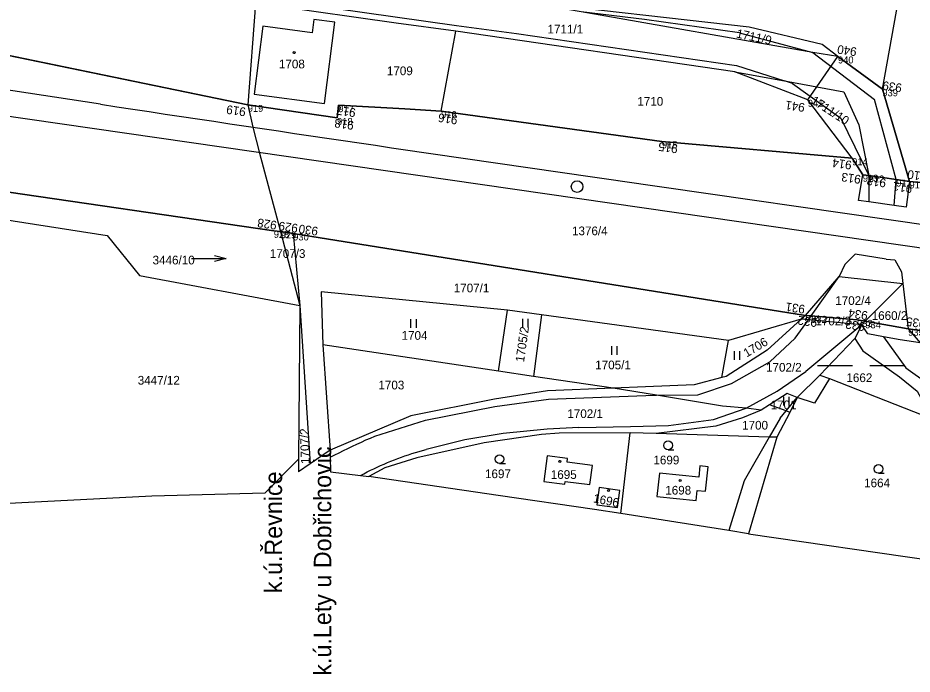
# Model space of a CAD drawing. Extents: x -757895 to -757311, y -1060303 to -1059942.
# Drawn here: x -757679.5 to -757525.5, y -1060222.2 to -1060109.2 of the extents above; entities that cross this region are included whole.
import ezdxf

# ---------------------------------------------------------------- set-up
doc = ezdxf.new("R2010")
doc.units = 0
for name, color, linetype in [('_SO 102 hektometry', 7, 'Continuous'), ('Dočasné zábory', 7, 'Continuous'), ('Obvod stavby', 7, 'Continuous'), ('Vrstva 1', 7, 'Continuous'), ('Vrstva 53', 7, 'Continuous'), ('Vrstva 55', 7, 'Continuous'), ('Vrstva 56', 7, 'Continuous'), ('Vrstva 57', 7, 'Continuous'), ('Vrstva 58', 7, 'Continuous'), ('Vrstva 59', 7, 'Continuous'), ('Vrstva 60', 7, 'Continuous')]:
    doc.layers.add(name, color=color, linetype=linetype)

msp = doc.modelspace()

# ---------------------------------------------------------------- linework, layer by layer
at = {"layer": '_SO 102 hektometry'}
msp.add_circle((-757583.22, -1060138.24), 1, dxfattribs=at)
at = {"layer": 'Dočasné zábory'}
msp.add_lwpolyline([(-757538.3, -1060115.83), (-757530.66, -1060121.48), (-757525.99, -1060137.35), (-757528.28, -1060137.03), (-757533.01, -1060136.32), (-757534.03, -1060136.19), (-757535.86, -1060133.35), (-757543.49, -1060123.29), (-757538.3, -1060115.83)], dxfattribs=at)
at = {"layer": 'Obvod stavby'}
for points in [[(-757420.49, -1060174.29), (-757417.66, -1060153.97), (-757419.22, -1060153.71), (-757450.04, -1060148.6), (-757493.93, -1060141.33), (-757496.99, -1060140.91), (-757515.4, -1060138.37), (-757520.85, -1060137.84), (-757523.49, -1060137.59), (-757525.99, -1060137.35), (-757528.28, -1060137.03), (-757533.01, -1060136.32), (-757534.03, -1060136.19), (-757535.86, -1060133.35), (-757568.62, -1060130.44), (-757606.63, -1060125.23), (-757624.32, -1060124.22), (-757624.54, -1060126.42), (-757639.93, -1060124.17), (-757687.19, -1060114.38)], [(-757686.64, -1060138.39), (-757635.44, -1060145.86), (-757634.26, -1060145.96), (-757632.1, -1060146.3), (-757543.88, -1060160.4), (-757542.9, -1060160.49), (-757535.01, -1060161.18), (-757533.6, -1060161.43), (-757526.21, -1060162.71), (-757513.1, -1060164.5), (-757470.38, -1060167.04), (-757443.58, -1060171.99), (-757420.49, -1060174.29)]]:
    msp.add_lwpolyline(points, dxfattribs=at)
at = {"layer": 'Vrstva 1'}
for p, q in [((-757429.32, -1060162.53), (-757720.62, -1060120.47)), ((-757665.26, -1060124.05), (-757689.98, -1060120.32)), ((-757576.18, -1060137.2), (-757470.2, -1060152.45))]:
    msp.add_line(p, q, dxfattribs=at)
msp.add_arc((-755796.09, -1047764.6), 12500, 261.400126, 261.812855, dxfattribs=at)
at = {"layer": 'Vrstva 53'}
for points in [[(-757687.19, -1060114.38), (-757639.93, -1060124.17), (-757624.54, -1060126.42), (-757624.32, -1060124.22), (-757612.89, -1060124.84), (-757606.63, -1060125.23), (-757568.62, -1060130.44), (-757535.86, -1060133.35), (-757534.03, -1060136.19), (-757533.01, -1060136.32), (-757528.28, -1060137.03), (-757525.99, -1060137.35), (-757523.49, -1060137.59), (-757520.85, -1060137.84), (-757515.4, -1060138.37), (-757496.99, -1060140.91), (-757493.93, -1060141.33), (-757450.04, -1060148.6), (-757417.66, -1060153.97), (-757412.43, -1060151.61), (-757391.89, -1060154.81), (-757390.25, -1060143), (-757387.56, -1060158.16)], [(-757328.56, -1060183.46), (-757338.29, -1060184.85), (-757361.91, -1060181.63), (-757443.58, -1060171.99), (-757470.38, -1060167.04), (-757513.1, -1060164.5), (-757526.21, -1060162.71), (-757533.6, -1060161.43), (-757535.01, -1060161.18), (-757542.9, -1060160.49), (-757543.88, -1060160.4), (-757632.1, -1060146.3), (-757634.26, -1060145.96), (-757635.44, -1060145.86), (-757686.64, -1060138.39), (-757693.18, -1060137.43), (-757732.62, -1060131.67), (-757793.56, -1060122.78), (-757866, -1060118.97)]]:
    msp.add_lwpolyline(points, dxfattribs=at)
at = {"layer": 'Vrstva 55'}
for p, q in [((-757638.59, -1060106.69), (-757639.93, -1060124.17)), ((-757638.59, -1060106.69), (-757639.93, -1060124.17)), ((-757530.66, -1060121.48), (-757527.8, -1060105.72)), ((-757606.63, -1060125.23), (-757604.11, -1060111.45)), ((-757556.06, -1060118.47), (-757604.11, -1060111.45)), ((-757687.19, -1060114.38), (-757639.93, -1060124.17)), ((-757530.66, -1060121.48), (-757538.3, -1060115.83)), ((-757525.99, -1060137.35), (-757530.66, -1060121.48)), ((-757634.26, -1060145.96), (-757632.1, -1060146.3)), ((-757634.26, -1060145.96), (-757630.94, -1060158.73)), ((-757634.26, -1060145.96), (-757630.94, -1060158.73)), ((-757632.1, -1060146.3), (-757543.88, -1060160.4)), ((-757632.1, -1060146.3), (-757630.94, -1060158.73)), ((-757527.15, -1060154.92), (-757533.6, -1060161.43)), ((-757527.15, -1060154.92), (-757526.21, -1060162.71)), ((-757630.94, -1060158.73), (-757631.18, -1060185.19)), ((-757630.94, -1060158.73), (-757631.18, -1060185.19)), ((-757630.94, -1060158.73), (-757629.16, -1060185.96)), ((-757596.77, -1060170), (-757595.21, -1060159.51)), ((-757589.33, -1060160.31), (-757595.21, -1060159.51)), ((-757589.33, -1060160.31), (-757590.73, -1060170.9)), ((-757557.15, -1060164.71), (-757589.33, -1060160.31)), ((-757543.88, -1060160.4), (-757544.63, -1060161.07)), ((-757544.63, -1060161.07), (-757557.15, -1060164.71)), ((-757534.18, -1060162.01), (-757535.4, -1060164.4)), ((-757533.6, -1060161.43), (-757534.18, -1060162.01)), ((-757533.6, -1060161.43), (-757526.21, -1060162.71)), ((-757526.21, -1060162.71), (-757513.1, -1060164.5)), ((-757558.32, -1060171.12), (-757557.15, -1060164.71)), ((-757535.4, -1060164.4), (-757541.4, -1060170.7)), ((-757627, -1060165.49), (-757625.74, -1060183.63)), ((-757596.77, -1060170), (-757627, -1060165.49)), ((-757590.73, -1060170.9), (-757596.77, -1060170)), ((-757576.99, -1060172.95), (-757590.73, -1060170.9)), ((-757541.4, -1060170.7), (-757545.33, -1060174.55)), ((-757545.33, -1060174.55), (-757546.6, -1060177.1)), ((-757550.1, -1060175.8), (-757551.51, -1060176.74)), ((-757546.6, -1060177.1), (-757548.85, -1060181.4)), ((-757575.67, -1060194.52), (-757574.09, -1060180.62)), ((-757569.63, -1060180.73), (-757574.09, -1060180.62)), ((-757548.85, -1060181.4), (-757553.73, -1060197.99)), ((-757625.74, -1060183.63), (-757629.16, -1060185.96)), ((-757631.18, -1060185.19), (-757636.9, -1060190.98)), ((-757631.18, -1060185.19), (-757631.2, -1060187.35)), ((-757629.16, -1060185.96), (-757631.2, -1060187.35)), ((-757596.81, -1060191.42), (-757619.09, -1060188.12)), ((-757580.24, -1060193.85), (-757596.81, -1060191.42)), ((-757575.67, -1060194.52), (-757580.24, -1060193.85)), ((-757553.73, -1060197.99), (-757501.45, -1060205.62))]:
    msp.add_line(p, q, dxfattribs=at)
for points in [[(-757643.18, -1060052.41), (-757642.66, -1060069.92), (-757642.17, -1060087.53), (-757638.59, -1060106.69), (-757639.93, -1060124.17), (-757639.03, -1060128.02), (-757637.9, -1060132.49), (-757634.26, -1060145.96), (-757630.94, -1060158.73), (-757631.18, -1060185.19), (-757631.2, -1060187.35)], [(-757538.3, -1060115.83), (-757542.65, -1060115.17), (-757582.51, -1060108.15), (-757593.23, -1060106.29)], [(-757538.3, -1060115.83), (-757541.05, -1060113.79), (-757553.6, -1060110.8), (-757593.23, -1060106.29)], [(-757604.11, -1060111.45), (-757614.37, -1060110.07), (-757635.45, -1060107.13)], [(-757637.32, -1060110.63), (-757638.83, -1060122.33), (-757626.73, -1060123.9), (-757624.93, -1060109.9), (-757628.52, -1060109.44), (-757628.82, -1060111.73), (-757637.32, -1060110.63)], [(-757535.86, -1060133.35), (-757543.49, -1060123.29), (-757556.06, -1060118.47)], [(-757556.06, -1060118.47), (-757547.51, -1060120.04), (-757537.32, -1060121.92), (-757534.73, -1060127.58), (-757533.01, -1060136.32)], [(-757606.63, -1060125.23), (-757612.89, -1060124.84), (-757624.32, -1060124.22), (-757624.54, -1060126.42), (-757639.93, -1060124.17)], [(-757639.93, -1060124.17), (-757639.03, -1060128.02), (-757637.9, -1060132.49), (-757634.26, -1060145.96)], [(-757639.93, -1060124.17), (-757639.03, -1060128.02), (-757637.9, -1060132.49), (-757634.26, -1060145.96)], [(-757535.86, -1060133.35), (-757568.62, -1060130.44), (-757606.63, -1060125.23)], [(-757533.01, -1060136.32), (-757534.03, -1060136.19), (-757535.86, -1060133.35)], [(-757525.99, -1060137.35), (-757528.28, -1060137.03), (-757533.01, -1060136.32)], [(-757515.4, -1060138.37), (-757518.94, -1060138.03), (-757520.85, -1060137.84), (-757523.49, -1060137.59), (-757525.99, -1060137.35)], [(-757634.26, -1060145.96), (-757635.44, -1060145.86), (-757686.64, -1060138.39)], [(-757686.61, -1060143.18), (-757664.14, -1060146.65), (-757658.56, -1060153.53), (-757630.94, -1060158.73)], [(-757543.88, -1060160.4), (-757538.07, -1060153.7), (-757527.15, -1060154.92)], [(-757595.21, -1060159.51), (-757627.27, -1060156.33), (-757627, -1060165.49)], [(-757533.6, -1060161.43), (-757535.01, -1060161.18), (-757542.9, -1060160.49), (-757543.88, -1060160.4)], [(-757544.63, -1060161.07), (-757550.52, -1060166.39), (-757557.55, -1060170.92), (-757558.32, -1060171.12)], [(-757534.18, -1060162.01), (-757543.4, -1060161.18), (-757544.63, -1060161.07)], [(-757530.47, -1060164.08), (-757533.19, -1060163.6), (-757534.18, -1060162.01)], [(-757535.4, -1060164.4), (-757534.05, -1060166.5), (-757527.72, -1060171), (-757524.67, -1060173.45), (-757522.06, -1060178.2)], [(-757530.47, -1060164.08), (-757526.6, -1060169.42), (-757519.47, -1060174.52), (-757512.04, -1060178.07), (-757508.94, -1060181.82), (-757502, -1060190.6), (-757494.7, -1060204.13)], [(-757512.14, -1060167.1), (-757524.18, -1060165.15), (-757527.62, -1060164.59), (-757530.47, -1060164.08)], [(-757558.32, -1060171.12), (-757563.04, -1060172.38), (-757571.43, -1060172.73), (-757576.99, -1060172.95)], [(-757541.4, -1060170.7), (-757539.76, -1060171.25), (-757522.06, -1060178.2)], [(-757576.99, -1060172.95), (-757588.33, -1060173.41), (-757597.42, -1060174.85), (-757611.84, -1060177.68), (-757625.74, -1060183.63)], [(-757551.51, -1060176.74), (-757554.09, -1060176.38), (-757558.16, -1060176.02), (-757569.54, -1060174.17), (-757576.99, -1060172.95)], [(-757545.33, -1060174.55), (-757547.04, -1060173.83), (-757550.1, -1060175.8)], [(-757546.6, -1060177.1), (-757547.24, -1060176.86), (-757550.1, -1060175.8)], [(-757551.51, -1060176.74), (-757554.73, -1060178.07), (-757559.36, -1060179.48), (-757569.63, -1060180.73)], [(-757574.09, -1060180.62), (-757586.32, -1060180.67), (-757589.35, -1060180.9), (-757599.24, -1060182.35), (-757610.82, -1060184.91), (-757616.3, -1060186.63), (-757619.09, -1060188.12)], [(-757548.85, -1060181.4), (-757550.13, -1060181.36), (-757569.63, -1060180.73)], [(-757625.74, -1060183.63), (-757625.72, -1060184.84), (-757625.67, -1060187.37)], [(-757580.59, -1060186.26), (-757584.93, -1060185.69), (-757584.85, -1060185.07), (-757588.36, -1060184.6), (-757588.94, -1060189.01), (-757585.35, -1060189.49), (-757585.29, -1060188.99), (-757581.03, -1060189.55), (-757580.59, -1060186.26)], [(-757569.05, -1060187.55), (-757569.49, -1060191.57), (-757562.71, -1060192.3), (-757562.52, -1060190.53), (-757561.12, -1060190.68), (-757560.66, -1060186.46), (-757562.06, -1060186.31), (-757562.27, -1060188.28), (-757569.05, -1060187.55)], [(-757625.67, -1060187.37), (-757620.5, -1060187.96), (-757619.09, -1060188.12)], [(-757684.44, -1060192.89), (-757656.46, -1060191.47), (-757636.9, -1060190.98)], [(-757579.43, -1060190.03), (-757579.85, -1060193), (-757576.28, -1060193.51), (-757575.85, -1060190.54), (-757579.43, -1060190.03)], [(-757553.73, -1060197.99), (-757557.09, -1060197.46), (-757573.5, -1060194.87), (-757575.67, -1060194.52)]]:
    msp.add_lwpolyline(points, dxfattribs=at)
at = {"layer": 'Vrstva 56'}
for p, q in [((-757625.12, -1060107.53), (-757604, -1060110.48)), ((-757571.64, -1060109.48), (-757582.51, -1060108.15)), ((-757555.27, -1060111.76), (-757571.64, -1060109.48)), ((-757604, -1060110.48), (-757593.68, -1060111.85)), ((-757593.68, -1060111.85), (-757555.79, -1060117.41)), ((-757555.27, -1060111.76), (-757542.65, -1060115.17)), ((-757542.65, -1060115.17), (-757532.02, -1060123.21)), ((-757555.79, -1060117.41), (-757547.51, -1060120.04)), ((-757546.14, -1060120.48), (-757547.51, -1060120.04)), ((-757546.14, -1060120.48), (-757537.81, -1060126.43)), ((-757528.28, -1060137.03), (-757532.02, -1060123.21)), ((-757537.81, -1060126.43), (-757533.01, -1060136.32)), ((-757534.76, -1060140.62), (-757534.03, -1060136.19)), ((-757533.01, -1060136.32), (-757532.98, -1060140.88)), ((-757528.61, -1060141.49), (-757528.28, -1060137.03)), ((-757525.99, -1060137.35), (-757526.57, -1060141.77)), ((-757532.98, -1060140.88), (-757534.76, -1060140.62)), ((-757528.61, -1060141.49), (-757532.98, -1060140.88)), ((-757526.57, -1060141.77), (-757528.61, -1060141.49)), ((-757535.34, -1060149.89), (-757537.11, -1060151.64)), ((-757530.01, -1060150.73), (-757535.34, -1060149.89)), ((-757530.01, -1060150.73), (-757528.53, -1060150.83)), ((-757528.53, -1060150.83), (-757527.39, -1060152.92)), ((-757537.11, -1060151.64), (-757538.07, -1060153.7)), ((-757527.39, -1060152.92), (-757527.15, -1060154.92)), ((-757542.9, -1060160.49), (-757538.07, -1060153.7)), ((-757543.4, -1060161.18), (-757542.9, -1060160.49)), ((-757545.65, -1060164.34), (-757543.4, -1060161.18)), ((-757534.18, -1060162.01), (-757543.82, -1060170.07)), ((-757526.21, -1060162.71), (-757524.18, -1060165.15)), ((-757550.01, -1060168.4), (-757545.65, -1060164.34)), ((-757556.62, -1060172.15), (-757550.01, -1060168.4)), ((-757548.76, -1060173.47), (-757543.82, -1060170.07)), ((-757539.76, -1060171.25), (-757542.34, -1060175.54)), ((-757562.46, -1060174.07), (-757556.62, -1060172.15)), ((-757588.16, -1060174.83), (-757571.4, -1060174.19)), ((-757571.4, -1060174.19), (-757569.54, -1060174.17)), ((-757569.54, -1060174.17), (-757562.46, -1060174.07)), ((-757554.09, -1060176.38), (-757548.76, -1060173.47)), ((-757547.24, -1060176.86), (-757545.33, -1060174.55)), ((-757542.34, -1060175.54), (-757545.33, -1060174.55)), ((-757609.33, -1060178.42), (-757597.39, -1060176.11)), ((-757597.39, -1060176.11), (-757588.16, -1060174.83)), ((-757559.73, -1060178.32), (-757554.09, -1060176.38)), ((-757548.27, -1060178.12), (-757547.24, -1060176.86)), ((-757618.02, -1060181.19), (-757609.33, -1060178.42)), ((-757567.48, -1060179.37), (-757559.73, -1060178.32)), ((-757548.27, -1060178.12), (-757550.13, -1060181.36)), ((-757595.94, -1060180.77), (-757602.57, -1060181.84)), ((-757588.4, -1060179.97), (-757595.94, -1060180.77)), ((-757582.91, -1060179.71), (-757588.4, -1060179.97)), ((-757582.91, -1060179.71), (-757574.04, -1060179.54)), ((-757574.04, -1060179.54), (-757567.48, -1060179.37)), ((-757602.57, -1060181.84), (-757609.19, -1060183.49)), ((-757550.13, -1060181.36), (-757554.44, -1060188.87)), ((-757554.44, -1060188.87), (-757557.09, -1060197.46))]:
    msp.add_line(p, q, dxfattribs=at)
for points in [[(-757625.72, -1060184.84), (-757624.96, -1060184.44), (-757624.21, -1060184.05), (-757623.45, -1060183.67), (-757622.68, -1060183.3), (-757621.91, -1060182.93), (-757621.14, -1060182.57), (-757620.36, -1060182.21), (-757619.59, -1060181.86), (-757618.8, -1060181.52), (-757618.02, -1060181.19)], [(-757620.5, -1060187.96), (-757619.93, -1060187.66), (-757619.36, -1060187.36), (-757618.79, -1060187.08), (-757618.21, -1060186.8), (-757617.63, -1060186.53), (-757617.05, -1060186.26), (-757616.46, -1060186), (-757615.87, -1060185.75), (-757615.28, -1060185.51), (-757614.68, -1060185.27), (-757614.08, -1060185.05), (-757613.48, -1060184.82), (-757612.87, -1060184.61), (-757612.26, -1060184.41), (-757611.65, -1060184.21), (-757611.04, -1060184.02), (-757610.43, -1060183.83), (-757609.81, -1060183.66), (-757609.19, -1060183.49)]]:
    msp.add_lwpolyline(points, dxfattribs=at)
at = {"layer": 'Vrstva 58'}
for p, q in [((-757649.63, -1060150.62), (-757643.63, -1060150.62)), ((-757611.9, -1060161.05), (-757611.9, -1060162.55)), ((-757610.9, -1060162.55), (-757610.9, -1060161.05)), ((-757592.64, -1060161.02), (-757592.64, -1060162.52)), ((-757591.64, -1060162.52), (-757591.64, -1060161.02)), ((-757577.3, -1060165.68), (-757577.3, -1060167.18)), ((-757576.3, -1060167.18), (-757576.3, -1060165.68)), ((-757556.2, -1060166.55), (-757556.2, -1060168.05)), ((-757555.2, -1060168.05), (-757555.2, -1060166.55)), ((-757541.83, -1060169.03), (-757535.83, -1060169.03)), ((-757532.83, -1060169.03), (-757526.83, -1060169.03)), ((-757547.68, -1060174.43), (-757547.68, -1060175.93)), ((-757546.68, -1060175.93), (-757546.68, -1060174.43)), ((-757567.56, -1060183.53), (-757566.56, -1060183.53)), ((-757596.57, -1060185.91), (-757595.57, -1060185.91)), ((-757531.34, -1060187.6), (-757530.34, -1060187.6))]:
    msp.add_line(p, q, dxfattribs=at)
msp.add_lwpolyline([(-757645.63, -1060150.12), (-757643.63, -1060150.62), (-757645.63, -1060151.12)], dxfattribs=at)
for centre in [(-757567.56, -1060182.78), (-757596.57, -1060185.16), (-757531.34, -1060186.85)]:
    msp.add_circle(centre, 0.75, dxfattribs=at)
at = {"layer": 'Vrstva 59'}
for centre in [(-757631.95, -1060115.17), (-757586.19, -1060185.54), (-757565.49, -1060188.83), (-757577.81, -1060190.55)]:
    msp.add_circle(centre, 0.175, dxfattribs=at)
at = {"layer": 'Vrstva 60'}
for p, q in [((-757538.3, -1060115.83), (-757538.3, -1060115.83)), ((-757530.66, -1060121.48), (-757530.66, -1060121.48)), ((-757543.49, -1060123.29), (-757543.49, -1060123.29)), ((-757639.93, -1060124.17), (-757639.93, -1060124.17)), ((-757624.32, -1060124.22), (-757624.32, -1060124.22)), ((-757606.63, -1060125.23), (-757606.63, -1060125.23)), ((-757624.54, -1060126.42), (-757624.54, -1060126.42)), ((-757568.62, -1060130.44), (-757568.62, -1060130.44)), ((-757535.86, -1060133.35), (-757535.86, -1060133.35)), ((-757534.03, -1060136.19), (-757534.03, -1060136.19)), ((-757533.01, -1060136.32), (-757533.01, -1060136.32)), ((-757528.28, -1060137.03), (-757528.28, -1060137.03)), ((-757525.99, -1060137.35), (-757525.99, -1060137.35)), ((-757635.44, -1060145.86), (-757635.44, -1060145.86)), ((-757634.26, -1060145.96), (-757634.26, -1060145.96)), ((-757632.1, -1060146.3), (-757632.1, -1060146.3)), ((-757543.88, -1060160.4), (-757543.88, -1060160.4)), ((-757542.9, -1060160.49), (-757542.9, -1060160.49)), ((-757535.01, -1060161.18), (-757535.01, -1060161.18)), ((-757533.6, -1060161.43), (-757533.6, -1060161.43)), ((-757526.21, -1060162.71), (-757526.21, -1060162.71))]:
    msp.add_line(p, q, dxfattribs=at)

# ---------------------------------------------------------------- texts
at = {"layer": 'Dočasné zábory'}
for s, p in [('940', (-757534.99, -1060114.31)), ('939', (-757527.21, -1060120.54)), ('941', (-757543.92, -1060123.91))]:
    msp.add_text(s, height=1.5, rotation=171.7882, dxfattribs=at).set_placement(p)
at = {"layer": 'Obvod stavby'}
for s, p in [('919', (-757640.17, -1060124.67)), ('917', (-757621.25, -1060124.81)), ('918', (-757621.57, -1060127)), ('916', (-757603.71, -1060126.07)), ('915', (-757565.8, -1060131.05)), ('914', (-757535.85, -1060133.84)), ('913', (-757534.28, -1060136.29)), ('910', (-757522.92, -1060135.83)), ('912', (-757529.93, -1060136.92)), ('911', (-757525.41, -1060137.9)), ('928', (-757634.84, -1060144.19)), ('929', (-757631.19, -1060144.71)), ('930', (-757627.73, -1060145.22)), ('931', (-757543.89, -1060158.65)), ('932', (-757541.8, -1060160.96)), ('934', (-757533.08, -1060159.74)), ('935', (-757523.15, -1060161.17)), ('933', (-757533.58, -1060161.65))]:
    msp.add_text(s, height=1.5, rotation=171.7882, dxfattribs=at).set_placement(p)
at = {"layer": 'Vrstva 55'}
for s, p in [('k.ú.Lety u Dobřichovic', (-757625.55, -1060222.44)), ('k.ú.Řevnice', (-757634.02, -1060208.23))]:
    msp.add_text(s, height=3, rotation=90, dxfattribs=at).set_placement(p)
at = {"layer": 'Vrstva 57'}
for s, p in [('1711/1', (-757588.32, -1060111.87)), ('1708', (-757634.56, -1060117.88)), ('1709', (-757615.97, -1060119.05)), ('1710', (-757572.85, -1060124.31)), ('1376/4', (-757584.1, -1060146.61)), ('1707/3', (-757636.13, -1060150.51)), ('3446/10', (-757656.31, -1060151.63)), ('1707/1', (-757604.46, -1060156.44)), ('1702/4', (-757538.77, -1060158.61)), ('1702/3', (-757542.2, -1060162.13)), ('1660/2', (-757532.5, -1060161.19)), ('1704', (-757613.44, -1060164.61)), ('1705/1', (-757580.1, -1060169.69)), ('1702/2', (-757550.69, -1060170.1)), ('3447/12', (-757658.87, -1060172.33)), ('1662', (-757536.85, -1060171.89)), ('1703', (-757617.43, -1060173.15)), ('1701', (-757549.9, -1060176.57)), ('1702/1', (-757584.9, -1060178.08)), ('1700', (-757554.81, -1060180.07)), ('1699', (-757570.08, -1060186.06)), ('1697', (-757599.08, -1060188.43)), ('1695', (-757587.75, -1060188.56)), ('1664', (-757533.8, -1060190)), ('1698', (-757568.04, -1060191.26))]:
    msp.add_text(s, height=1.5, dxfattribs=at).set_placement(p)
for s, rotation, p in [('1711/9', 348, (-757555.9, -1060112.55)), ('1711/10', 327, (-757543.09, -1060123.76)), ('1705/2', 82, (-757592.36, -1060168.52)), ('1706', 31, (-757554.03, -1060167.68)), ('1707/2', 92, (-757629.25, -1060185.96)), ('1696', 349, (-757580.55, -1060192.58))]:
    msp.add_text(s, height=1.5, rotation=rotation, dxfattribs=at).set_placement(p)
at = {"layer": 'Vrstva 60'}
for s, p in [('940', (-757538.3, -1060117.03)), ('939', (-757530.66, -1060122.68)), ('941', (-757543.49, -1060124.49)), ('919', (-757639.93, -1060125.37)), ('917', (-757624.32, -1060125.42)), ('916', (-757606.63, -1060126.43)), ('918', (-757624.54, -1060127.62)), ('915', (-757568.62, -1060131.64)), ('914', (-757535.86, -1060134.55)), ('913', (-757534.03, -1060137.39)), ('912', (-757533.01, -1060137.52)), ('911', (-757528.28, -1060138.23)), ('910', (-757525.99, -1060138.55)), ('928', (-757635.44, -1060147.06)), ('929', (-757634.26, -1060147.16)), ('930', (-757632.1, -1060147.5)), ('931', (-757543.88, -1060161.6)), ('932', (-757542.9, -1060161.69)), ('933', (-757535.01, -1060162.38)), ('934', (-757533.6, -1060162.63)), ('935', (-757526.21, -1060163.91))]:
    msp.add_text(s, height=1.2, dxfattribs=at).set_placement(p)

doc.saveas('drawing.dxf')
